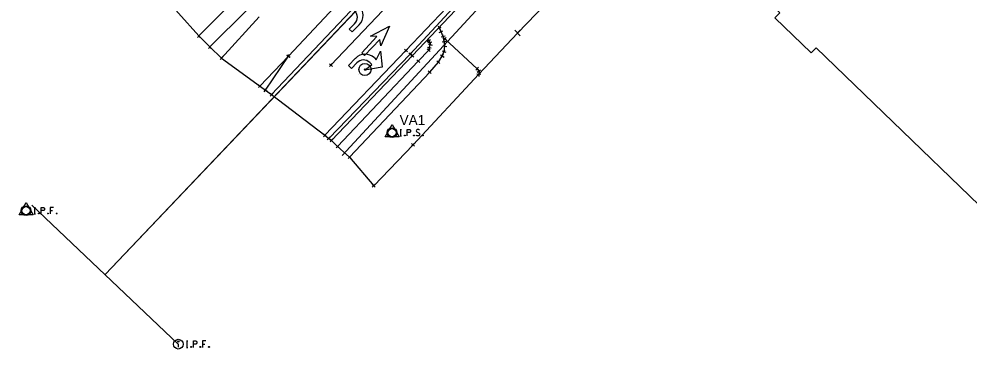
# Model space of a CAD drawing. Extents: x 1475580 to 1482245, y 377937 to 382467.
# Drawn here: x 1481226 to 1481461, y 377994.7 to 378076.4 of the extents above; entities that cross this region are included whole.
import ezdxf

# ---------------------------------------------------------------- set-up
doc = ezdxf.new("R2010")
doc.units = 0
for name, color, linetype in [('Default', 7, 'Continuous'), ('DT_X_Contour_Minor', 7, 'Continuous'), ('DT_X_Void', 7, 'Continuous'), ('PM_X_Channelizing_Line', 7, 'Continuous'), ('PM_X_Crosswalk', 7, 'Continuous'), ('PM_X_Lane_Line', 7, 'Continuous'), ('PV_X_Curb', 7, 'Continuous'), ('RD_X_Cells', 7, 'Continuous'), ('RD_X_Concrete_Pad', 7, 'Continuous'), ('RS_Raster1', 7, 'Continuous'), ('SG_X_Poles', 7, 'Continuous'), ('SV_P_Mon_Cells_Set', 7, 'Continuous'), ('SV_X_Break_Lines', 7, 'Continuous'), ('SV_X_Shot_Marker', 7, 'Continuous'), ('SV_X_Text_Description', 7, 'Continuous'), ('SV_X_Top_of_Bank', 7, 'Continuous'), ('UT_X_Gas_Cells', 7, 'Continuous'), ('UT_X_Telecom_Cells', 7, 'Continuous'), ('XS_X_Ground_Line', 7, 'Continuous')]:
    doc.layers.add(name, color=color, linetype=linetype)

msp = doc.modelspace()

# ---------------------------------------------------------------- linework, layer by layer
at = {"layer": 'Default'}
for p, q in [((1481247.31, 378013.07), (1481453.81, 378230.68)), ((1481229.17, 378030.28), (1481265.44, 377995.86))]:
    msp.add_line(p, q, dxfattribs=at)
at = {"layer": 'DT_X_Contour_Minor'}
for points in [[(1481320.33, 378049.03), (1481320.68, 378049.03)], [(1481320.5, 378047.43), (1481320.5, 378049.03)], [(1481321.46, 378047.64), (1481321.52, 378047.64), (1481321.55, 378047.62), (1481321.58, 378047.57), (1481321.58, 378047.5), (1481321.55, 378047.45), (1481321.52, 378047.43), (1481321.46, 378047.43), (1481321.43, 378047.45), (1481321.4, 378047.5), (1481321.4, 378047.57), (1481321.43, 378047.62), (1481321.46, 378047.64)], [(1481322.07, 378047.43), (1481322.07, 378049.03), (1481322.6, 378049.03), (1481322.65, 378049.01), (1481322.73, 378048.99), (1481322.76, 378048.96), (1481322.8, 378048.94), (1481322.84, 378048.88), (1481322.87, 378048.81), (1481322.89, 378048.71), (1481322.89, 378048.56), (1481322.88, 378048.51), (1481322.86, 378048.44), (1481322.82, 378048.35), (1481322.77, 378048.31), (1481322.74, 378048.28), (1481322.69, 378048.26), (1481322.6, 378048.25), (1481322.07, 378048.25)], [(1481323.71, 378047.64), (1481323.77, 378047.64), (1481323.8, 378047.62), (1481323.83, 378047.57), (1481323.83, 378047.5), (1481323.8, 378047.45), (1481323.77, 378047.43), (1481323.71, 378047.43), (1481323.68, 378047.45), (1481323.64, 378047.5), (1481323.64, 378047.57), (1481323.68, 378047.62), (1481323.71, 378047.64)], [(1481325.08, 378048.91), (1481325.06, 378048.94), (1481325.02, 378048.96), (1481324.92, 378049), (1481324.8, 378049.03), (1481324.71, 378049.03), (1481324.68, 378049.03), (1481324.54, 378048.99), (1481324.42, 378048.91), (1481324.34, 378048.81), (1481324.32, 378048.71), (1481324.32, 378048.64), (1481324.34, 378048.54), (1481324.43, 378048.45), (1481325.03, 378048.07), (1481325.09, 378048.02), (1481325.11, 378047.97), (1481325.13, 378047.89), (1481325.13, 378047.82), (1481325.12, 378047.74), (1481325.11, 378047.69), (1481325.09, 378047.63), (1481325.07, 378047.58), (1481325.04, 378047.54), (1481325.01, 378047.5), (1481324.98, 378047.48), (1481324.93, 378047.45), (1481324.9, 378047.44), (1481324.8, 378047.43), (1481324.65, 378047.43), (1481324.55, 378047.45), (1481324.4, 378047.54), (1481324.32, 378047.62)], [(1481325.89, 378047.64), (1481325.95, 378047.64), (1481325.98, 378047.62), (1481326.01, 378047.57), (1481326.01, 378047.5), (1481325.98, 378047.45), (1481325.95, 378047.43), (1481325.89, 378047.43), (1481325.86, 378047.45), (1481325.83, 378047.5), (1481325.83, 378047.57), (1481325.86, 378047.62), (1481325.89, 378047.64)], [(1481320.33, 378047.43), (1481320.68, 378047.43)]]:
    msp.add_lwpolyline(points, dxfattribs=at)
msp.add_circle((1481318.31, 378048.23), 1.2, dxfattribs=at)
at = {"layer": 'DT_X_Void'}
for p, q in [((1481316.58, 378047.23), (1481318.31, 378050.23)), ((1481318.31, 378050.23), (1481320.04, 378047.23)), ((1481318.31, 378048.23), (1481318.31, 378048.23)), ((1481320.04, 378047.23), (1481316.58, 378047.23)), ((1481226.04, 378027.92), (1481227.77, 378030.92)), ((1481227.77, 378030.92), (1481229.5, 378027.92)), ((1481227.77, 378028.92), (1481227.77, 378028.92)), ((1481229.5, 378027.92), (1481226.04, 378027.92))]:
    msp.add_line(p, q, dxfattribs=at)
for centre in [(1481318.31, 378048.23), (1481227.77, 378028.92)]:
    msp.add_circle(centre, 1, dxfattribs=at)
at = {"layer": 'PM_X_Channelizing_Line'}
msp.add_line((1481247.31, 378013.07), (1481453.74, 378230.61), dxfattribs=at)
at = {"layer": 'PM_X_Crosswalk'}
msp.add_line((1481265.44, 377995.97), (1481265.44, 377995.09), dxfattribs=at)
for points in [[(1481229.78, 378029.72), (1481230.14, 378029.72)], [(1481229.96, 378028.12), (1481229.96, 378029.72)], [(1481231.52, 378028.12), (1481231.52, 378029.72), (1481232.05, 378029.72), (1481232.11, 378029.7), (1481232.19, 378029.68), (1481232.22, 378029.65), (1481232.25, 378029.63), (1481232.3, 378029.56), (1481232.33, 378029.5), (1481232.35, 378029.4), (1481232.35, 378029.25), (1481232.34, 378029.2), (1481232.32, 378029.12), (1481232.27, 378029.04), (1481232.23, 378029), (1481232.2, 378028.97), (1481232.14, 378028.95), (1481232.05, 378028.93), (1481231.52, 378028.93)], [(1481234.53, 378029.72), (1481233.77, 378029.72), (1481233.77, 378028.12)], [(1481233.77, 378028.93), (1481234.31, 378028.93)], [(1481229.78, 378028.12), (1481230.14, 378028.12)], [(1481230.92, 378028.33), (1481230.97, 378028.33), (1481231.01, 378028.3), (1481231.04, 378028.25), (1481231.04, 378028.19), (1481231.01, 378028.14), (1481230.97, 378028.12), (1481230.92, 378028.12), (1481230.89, 378028.14), (1481230.85, 378028.19), (1481230.85, 378028.25), (1481230.89, 378028.3), (1481230.92, 378028.33)], [(1481233.17, 378028.33), (1481233.22, 378028.33), (1481233.26, 378028.3), (1481233.29, 378028.25), (1481233.29, 378028.19), (1481233.26, 378028.14), (1481233.22, 378028.12), (1481233.17, 378028.12), (1481233.13, 378028.14), (1481233.1, 378028.19), (1481233.1, 378028.25), (1481233.13, 378028.3), (1481233.17, 378028.33)], [(1481235.32, 378028.33), (1481235.37, 378028.33), (1481235.4, 378028.3), (1481235.44, 378028.25), (1481235.44, 378028.19), (1481235.4, 378028.14), (1481235.37, 378028.12), (1481235.32, 378028.12), (1481235.28, 378028.14), (1481235.25, 378028.19), (1481235.25, 378028.25), (1481235.28, 378028.3), (1481235.32, 378028.33)], [(1481267.47, 377996.66), (1481267.82, 377996.66)], [(1481267.65, 377995.06), (1481267.65, 377996.66)], [(1481269.21, 377995.06), (1481269.21, 377996.66), (1481269.74, 377996.66), (1481269.8, 377996.65), (1481269.87, 377996.62), (1481269.91, 377996.59), (1481269.94, 377996.57), (1481269.98, 377996.51), (1481270.02, 377996.44), (1481270.04, 377996.34), (1481270.04, 377996.19), (1481270.03, 377996.14), (1481270.01, 377996.07), (1481269.96, 377995.98), (1481269.92, 377995.94), (1481269.88, 377995.91), (1481269.83, 377995.89), (1481269.74, 377995.88), (1481269.21, 377995.88)], [(1481272.22, 377996.66), (1481271.46, 377996.66), (1481271.46, 377995.06)], [(1481271.46, 377995.88), (1481272, 377995.88)], [(1481267.47, 377995.06), (1481267.82, 377995.06)], [(1481268.61, 377995.27), (1481268.66, 377995.27), (1481268.69, 377995.25), (1481268.73, 377995.2), (1481268.73, 377995.13), (1481268.69, 377995.08), (1481268.66, 377995.06), (1481268.61, 377995.06), (1481268.57, 377995.08), (1481268.54, 377995.13), (1481268.54, 377995.2), (1481268.57, 377995.25), (1481268.61, 377995.27)], [(1481270.85, 377995.27), (1481270.91, 377995.27), (1481270.94, 377995.25), (1481270.98, 377995.2), (1481270.98, 377995.13), (1481270.94, 377995.08), (1481270.91, 377995.06), (1481270.85, 377995.06), (1481270.82, 377995.08), (1481270.79, 377995.13), (1481270.79, 377995.2), (1481270.82, 377995.25), (1481270.85, 377995.27)], [(1481273, 377995.27), (1481273.06, 377995.27), (1481273.09, 377995.25), (1481273.13, 377995.2), (1481273.13, 377995.13), (1481273.09, 377995.08), (1481273.06, 377995.06), (1481273, 377995.06), (1481272.97, 377995.08), (1481272.94, 377995.13), (1481272.94, 377995.2), (1481272.97, 377995.25), (1481273, 377995.27)]]:
    msp.add_lwpolyline(points, dxfattribs=at)
for centre, radius in [((1481227.77, 378028.92), 1.2), ((1481265.44, 377995.86), 1.2), ((1481265.44, 377996.51), 0.16)]:
    msp.add_circle(centre, radius, dxfattribs=at)
at = {"layer": 'PM_X_Lane_Line'}
for radius in [1.5, 0.16]:
    msp.add_circle((1481311.61, 378063.87), radius, dxfattribs=at)
at = {"layer": 'PV_X_Curb'}
for p, q in [((1481348.7, 378072.23), (1481350.03, 378073.57)), ((1481348.7, 378073.57), (1481350.03, 378072.23))]:
    msp.add_line(p, q, dxfattribs=at)
at = {"layer": 'RD_X_Cells'}
for points in [[(1481282.15, 378080.77), (1481282.47, 378078.67), (1481273.26, 378069.45)], [(1481270.51, 378072.17), (1481277.73, 378079.42)], [(1481307.8, 378042.17), (1481327.62, 378063.23), (1481329.77, 378065.7), (1481330.75, 378067.21), (1481331.17, 378068.31), (1481331.4, 378069.66), (1481331.24, 378070.8), (1481330.95, 378072.04), (1481330.45, 378073.2), (1481330.02, 378074.14)], [(1481304.85, 378044.79), (1481324.81, 378065.95), (1481327.4, 378068.63), (1481327.54, 378069.3), (1481327.76, 378070.04), (1481327.64, 378070.63), (1481327.41, 378071.03)]]:
    msp.add_lwpolyline(points, dxfattribs=at)
at = {"layer": 'RD_X_Concrete_Pad'}
for p, q in [((1481306.09, 378075.53), (1481306.09, 378075.53)), ((1481309.06, 378075.2), (1481307.74, 378073.88)), ((1481307.74, 378073.88), (1481308.45, 378073.17)), ((1481308.45, 378073.17), (1481310.2, 378074.93)), ((1481313, 378072.13), (1481317.71, 378074.56)), ((1481317.71, 378074.56), (1481315.52, 378069.74)), ((1481317.71, 378074.56), (1481317.71, 378074.56)), ((1481310.8, 378068.02), (1481314.59, 378072)), ((1481315.31, 378071.31), (1481311.52, 378067.33)), ((1481314.59, 378072), (1481313, 378072.13)), ((1481315.52, 378069.74), (1481315.31, 378071.31)), ((1481307.56, 378064.82), (1481309.26, 378066.63)), ((1481311.52, 378067.33), (1481310.8, 378068.02)), ((1481311.16, 378067.67), (1481311.16, 378067.67)), ((1481313.94, 378066.74), (1481314.42, 378066.28)), ((1481314.42, 378066.28), (1481315.47, 378068.37)), ((1481315.47, 378068.37), (1481315.47, 378068.37)), ((1481315.47, 378068.37), (1481315.9, 378064.45)), ((1481308.29, 378064.14), (1481307.56, 378064.82)), ((1481309.57, 378065.5), (1481308.29, 378064.14)), ((1481311.55, 378063.71), (1481313.33, 378065.11)), ((1481315.9, 378064.45), (1481311.55, 378063.71)), ((1481313.33, 378065.11), (1481312.82, 378065.6)), ((1481309.99, 378062.54), (1481309.99, 378062.54))]:
    msp.add_line(p, q, dxfattribs=at)
for centre, radius, start, end in [((1481307.43, 378076.82), 2.3, 315.1218, 45.1218), ((1481307.87, 378077.25), 3.28, 315.1218, 46.0303), ((1481311.65, 378064.38), 3.28, 45.8661, 136.7746), ((1481311.24, 378063.92), 2.3, 46.7746, 136.7746)]:
    msp.add_arc(centre, radius, start, end, dxfattribs=at)
at = {"layer": 'RS_Raster1'}
msp.add_lwpolyline([(1481331.4, 378071.43), (1481339.35, 378064.07), (1481339.77, 378063.43), (1481339.76, 378062.67), (1481323.5, 378045.22), (1481313.78, 378035.09)], dxfattribs=at)
at = {"layer": 'SG_X_Poles'}
msp.add_line((1481305.94, 378042.58), (1481449.51, 378198.14), dxfattribs=at)
at = {"layer": 'SV_P_Mon_Cells_Set'}
msp.add_lwpolyline([(1481451.97, 378161.26), (1481473.67, 378140.29), (1481475.51, 378142.19), (1481484.73, 378133.29), (1481482.89, 378131.39), (1481542.37, 378073.94), (1481514.51, 378045.1), (1481516.7, 378042.98), (1481507.91, 378033.89), (1481505.73, 378035.99), (1481482.51, 378011.95), (1481423.22, 378069.23), (1481422, 378067.97), (1481413.02, 378076.65), (1481414.23, 378077.9), (1481392.1, 378099.28)], close=True, dxfattribs=at)
at = {"layer": 'SV_X_Break_Lines'}
for points in [[(1481287, 378058.77), (1481292.67, 378067.17), (1481410.44, 378192.79)], [(1481285.64, 378059.75), (1481292.67, 378067.17)]]:
    msp.add_lwpolyline(points, dxfattribs=at)
at = {"layer": 'SV_X_Shot_Marker'}
msp.add_lwpolyline([(1481303.2, 378064.95), (1481417.43, 378185.28)], dxfattribs=at)
at = {"layer": 'SV_X_Text_Description'}
for points in [[(1481303.34, 378046.3), (1481323.37, 378067.29), (1481338.56, 378083.39), (1481347.15, 378092.37), (1481349.86, 378095.22), (1481353.76, 378099.33), (1481375.56, 378122.38), (1481398.53, 378146.5), (1481419.32, 378168.46), (1481422.39, 378171.69), (1481422.66, 378171.77), (1481425.76, 378173.1), (1481432.82, 378176.63), (1481435.17, 378177.85), (1481439.37, 378180.16), (1481442.87, 378182.19), (1481444.88, 378183.38), (1481447.26, 378184.55), (1481449.08, 378185.13), (1481451.1, 378185.28), (1481453.38, 378185.14), (1481456.17, 378184.44), (1481458.61, 378183.35), (1481462.63, 378180.74)], [(1481302.64, 378046.8), (1481322.8, 378067.68), (1481337.67, 378083.79), (1481346.36, 378092.91), (1481349.05, 378095.82), (1481353.05, 378099.83), (1481374.88, 378122.93), (1481397.86, 378147.13), (1481418.62, 378169.08), (1481421.74, 378172.17)]]:
    msp.add_lwpolyline(points, dxfattribs=at)
at = {"layer": 'SV_X_Top_of_Bank'}
msp.add_lwpolyline([(1481260.45, 378083.49), (1481270.51, 378072.17), (1481273.26, 378069.45), (1481276.1, 378066.71), (1481288.52, 378057.64), (1481301.7, 378047.6), (1481302.64, 378046.8), (1481303.34, 378046.3), (1481304.85, 378044.79), (1481307.8, 378042.17), (1481313.78, 378035.09), (1481323.5, 378045.22), (1481339.76, 378062.67), (1481349.36, 378072.9), (1481372.52, 378096.97)], dxfattribs=at)
at = {"layer": 'UT_X_Gas_Cells'}
for p, q in [((1481329.57, 378073.93), (1481330.47, 378074.35)), ((1481330.23, 378073.68), (1481329.81, 378074.59)), ((1481330, 378073.01), (1481330.91, 378073.4)), ((1481330.02, 378074.14), (1481330.02, 378074.14)), ((1481330.65, 378072.74), (1481330.26, 378073.66)), ((1481270.15, 378072.52), (1481270.86, 378071.81)), ((1481270.15, 378071.81), (1481270.86, 378072.52)), ((1481270.51, 378072.17), (1481270.51, 378072.17)), ((1481326.97, 378070.79), (1481327.84, 378071.28)), ((1481327.65, 378070.6), (1481327.16, 378071.47)), ((1481327.41, 378071.03), (1481327.41, 378071.03)), ((1481327.74, 378070.14), (1481327.53, 378071.11)), ((1481330.45, 378073.2), (1481330.45, 378073.2)), ((1481330.47, 378071.93), (1481331.44, 378072.16)), ((1481331.07, 378071.56), (1481330.84, 378072.53)), ((1481330.95, 378072.04), (1481330.95, 378072.04)), ((1481331.04, 378071.77), (1481331.77, 378071.09)), ((1481331.74, 378071.8), (1481331.07, 378071.07)), ((1481331.31, 378070.31), (1481331.17, 378071.3)), ((1481331.4, 378071.43), (1481331.4, 378071.43)), ((1481273.61, 378069.1), (1481272.9, 378069.81)), ((1481273.61, 378069.81), (1481272.9, 378069.1)), ((1481273.26, 378069.45), (1481273.26, 378069.45)), ((1481321.4, 378068.9), (1481322.12, 378068.21)), ((1481321.42, 378068.19), (1481322.11, 378068.92)), ((1481327.04, 378068.98), (1481327.76, 378068.29)), ((1481327.05, 378069.4), (1481328.03, 378069.21)), ((1481327.06, 378068.28), (1481327.75, 378068.99)), ((1481327.15, 378070.52), (1481328.13, 378070.73)), ((1481327.28, 378070.19), (1481328.24, 378069.9)), ((1481327.4, 378068.63), (1481327.4, 378068.63)), ((1481327.44, 378068.81), (1481327.63, 378069.79)), ((1481327.54, 378069.3), (1481327.54, 378069.3)), ((1481327.62, 378069.56), (1481327.91, 378070.52)), ((1481327.64, 378070.63), (1481327.64, 378070.63)), ((1481327.76, 378070.04), (1481327.76, 378070.04)), ((1481330.74, 378070.74), (1481331.73, 378070.87)), ((1481330.9, 378069.74), (1481331.89, 378069.57)), ((1481330.99, 378067.84), (1481331.35, 378068.77)), ((1481331.24, 378070.8), (1481331.24, 378070.8)), ((1481331.31, 378069.16), (1481331.48, 378070.15)), ((1481331.4, 378069.66), (1481331.4, 378069.66)), ((1481276.47, 378066.37), (1481275.73, 378067.05)), ((1481276.44, 378067.08), (1481275.76, 378066.34)), ((1481276.1, 378066.71), (1481276.1, 378066.71)), ((1481292.26, 378067.45), (1481293.09, 378066.89)), ((1481292.31, 378067.51), (1481293.04, 378066.83)), ((1481292.33, 378066.81), (1481293.02, 378067.53)), ((1481292.39, 378066.75), (1481292.95, 378067.58)), ((1481292.67, 378067.17), (1481292.67, 378067.17)), ((1481292.67, 378067.17), (1481292.67, 378067.17)), ((1481321.76, 378068.55), (1481321.76, 378068.55)), ((1481322.44, 378068.03), (1481323.16, 378067.34)), ((1481322.45, 378067.32), (1481323.15, 378068.04)), ((1481322.8, 378067.68), (1481322.8, 378067.68)), ((1481323.01, 378067.64), (1481323.73, 378066.95)), ((1481323.03, 378066.93), (1481323.72, 378067.66)), ((1481323.37, 378067.29), (1481323.37, 378067.29)), ((1481324.45, 378066.29), (1481325.17, 378065.6)), ((1481324.47, 378065.58), (1481325.15, 378066.31)), ((1481330.33, 378067.48), (1481331.17, 378066.93)), ((1481330.47, 378066.79), (1481331.02, 378067.63)), ((1481330.7, 378068.49), (1481331.64, 378068.13)), ((1481330.75, 378067.21), (1481330.75, 378067.21)), ((1481331.17, 378068.31), (1481331.17, 378068.31)), ((1481302.83, 378065.3), (1481303.56, 378064.61)), ((1481302.85, 378064.59), (1481303.54, 378065.32)), ((1481303.2, 378064.95), (1481303.2, 378064.95)), ((1481324.81, 378065.95), (1481324.81, 378065.95)), ((1481329.39, 378066.03), (1481330.15, 378065.37)), ((1481329.44, 378065.32), (1481330.1, 378066.08)), ((1481329.77, 378065.7), (1481329.77, 378065.7)), ((1481338.99, 378064.41), (1481339.72, 378063.74)), ((1481339.69, 378064.44), (1481339.01, 378063.71)), ((1481339.35, 378064.07), (1481339.35, 378064.07)), ((1481327.25, 378063.57), (1481327.98, 378062.88)), ((1481327.27, 378062.86), (1481327.96, 378063.59)), ((1481327.62, 378063.23), (1481327.62, 378063.23)), ((1481340.26, 378062.66), (1481339.26, 378062.68)), ((1481340.19, 378063.7), (1481339.35, 378063.16)), ((1481339.5, 378063.85), (1481340.05, 378063.01)), ((1481339.77, 378063.17), (1481339.75, 378062.17)), ((1481339.76, 378062.67), (1481339.76, 378062.67)), ((1481339.77, 378063.43), (1481339.77, 378063.43)), ((1481285.28, 378060.09), (1481286, 378059.41)), ((1481285.3, 378059.39), (1481285.99, 378060.11)), ((1481285.64, 378059.75), (1481285.64, 378059.75)), ((1481286.59, 378059.05), (1481287.42, 378058.49)), ((1481286.72, 378058.36), (1481287.28, 378059.19)), ((1481287, 378058.77), (1481287, 378058.77)), ((1481288.16, 378057.98), (1481288.89, 378057.29)), ((1481288.18, 378057.27), (1481288.87, 378058)), ((1481288.52, 378057.64), (1481288.52, 378057.64)), ((1481301.34, 378047.94), (1481302.06, 378047.25)), ((1481301.36, 378047.23), (1481302.05, 378047.96)), ((1481301.7, 378047.6), (1481301.7, 378047.6)), ((1481302.28, 378047.15), (1481302.99, 378046.45)), ((1481302.29, 378046.44), (1481302.98, 378047.16)), ((1481302.64, 378046.8), (1481302.64, 378046.8)), ((1481302.98, 378046.64), (1481303.7, 378045.95)), ((1481302.99, 378045.93), (1481303.68, 378046.66)), ((1481303.34, 378046.3), (1481303.34, 378046.3)), ((1481304.48, 378045.14), (1481305.21, 378044.45)), ((1481304.5, 378044.43), (1481305.19, 378045.16)), ((1481323.87, 378044.88), (1481323.14, 378045.56)), ((1481323.84, 378045.59), (1481323.16, 378044.85)), ((1481323.5, 378045.22), (1481323.5, 378045.22)), ((1481304.85, 378044.79), (1481304.85, 378044.79)), ((1481307.44, 378042.51), (1481308.17, 378041.82)), ((1481307.46, 378041.8), (1481308.14, 378042.53)), ((1481307.8, 378042.17), (1481307.8, 378042.17)), ((1481314.14, 378034.74), (1481313.42, 378035.43)), ((1481314.12, 378035.45), (1481313.43, 378034.73)), ((1481313.78, 378035.09), (1481313.78, 378035.09))]:
    msp.add_line(p, q, dxfattribs=at)
at = {"layer": 'UT_X_Telecom_Cells'}
msp.add_lwpolyline([(1481288.52, 378057.64), (1481353.24, 378126.12), (1481383.98, 378158.76), (1481429.27, 378206.31)], dxfattribs=at)
at = {"layer": 'XS_X_Ground_Line'}
for points in [[(1481301.7, 378047.6), (1481321.76, 378068.55), (1481336.83, 378084.47), (1481345.44, 378093.6), (1481348.33, 378096.64), (1481352.18, 378100.64), (1481374.04, 378123.71), (1481397.03, 378147.96), (1481417.78, 378169.81), (1481421, 378173.12), (1481421.99, 378172.29), (1481432.56, 378177.07), (1481434.87, 378178.29), (1481439.06, 378180.67), (1481442.5, 378182.61), (1481444.52, 378183.82), (1481446.99, 378184.96), (1481448.9, 378185.63), (1481451.06, 378185.83), (1481453.51, 378185.66), (1481456.36, 378184.91), (1481458.94, 378183.75), (1481462.96, 378181.17)], [(1481285.41, 378076.93), (1481276.1, 378066.71)]]:
    msp.add_lwpolyline(points, dxfattribs=at)

# ---------------------------------------------------------------- texts
at = {"layer": 'Default'}
msp.add_text('VA1', height=2.5, dxfattribs=at).set_placement((1481320.19, 378050.1))

doc.saveas('drawing.dxf')
